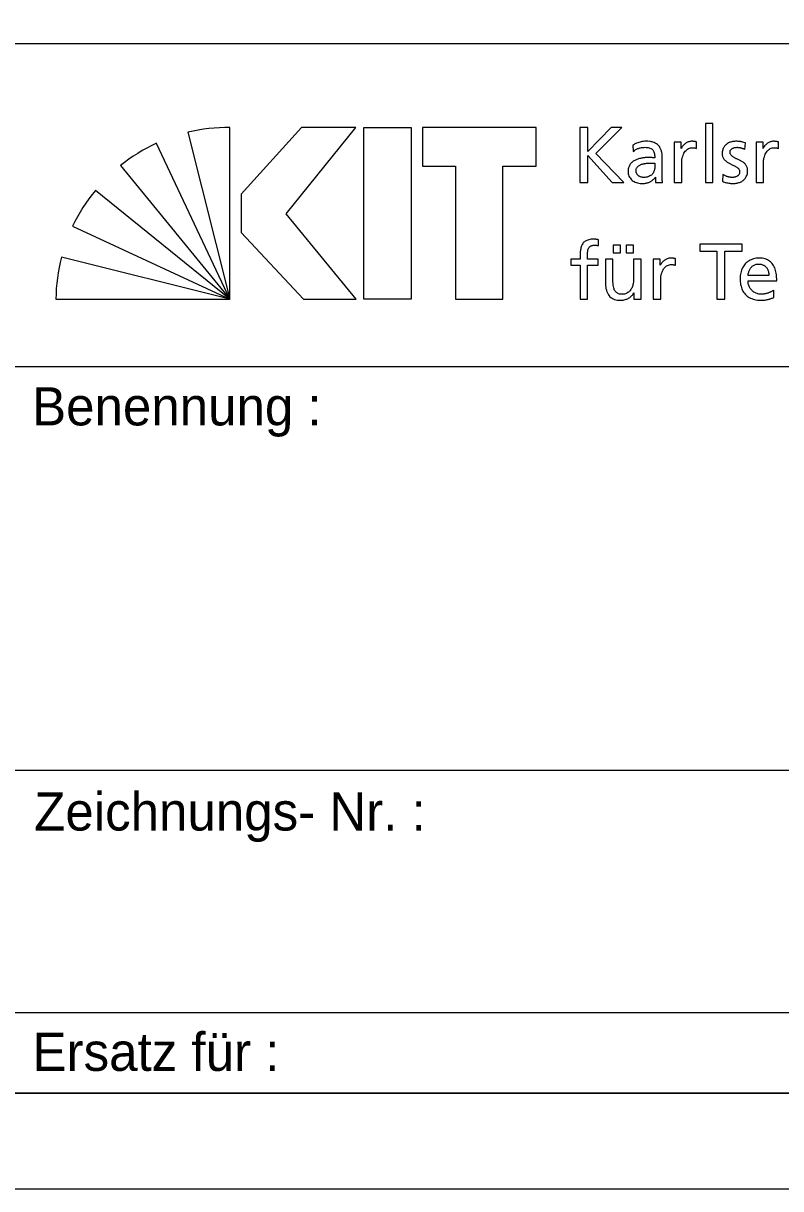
# Model space of a CAD drawing. Extents: x 0 to 23.8, y 0 to 16.8.
# Drawn here: x 22.013 to 22.807, y 0 to 1.221 of the extents above; entities that cross this region are included whole.
import ezdxf

# ---------------------------------------------------------------- set-up
doc = ezdxf.new("R2010")
doc.units = 0
doc.layers.add('90_Plankopf', color=7, linetype='Continuous')

msp = doc.modelspace()

# ---------------------------------------------------------------- linework, layer by layer
at = {"layer": '90_Plankopf'}
for p, q in [((20.1224, 1.1998), (23.68, 1.1998)), ((20.1224, 1.1998), (23.68, 1.1998)), ((22.2296, 0.9317), (22.2296, 1.1117)), ((22.5962, 1.1117), (22.5962, 1.0541)), ((22.1855, 1.1067), (22.2296, 0.9317)), ((22.2296, 0.9317), (22.1527, 1.095)), ((22.6516, 1.0932), (22.652, 1.0866)), ((22.7185, 1.0897), (22.7185, 1.0966)), ((22.7691, 1.0888), (22.7698, 1.0956)), ((22.8042, 1.0897), (22.8042, 1.0966)), ((22.6824, 1.0624), (22.6824, 1.0798)), ((22.1149, 1.0717), (22.2296, 0.9317)), ((22.6746, 1.0742), (22.6746, 1.0705)), ((22.7459, 1.0624), (22.7455, 1.0554)), ((22.5962, 1.0541), (22.6044, 1.0541)), ((22.6301, 1.0541), (22.6422, 1.0541)), ((22.2296, 0.9317), (22.0887, 1.0457)), ((22.0648, 1.0083), (22.2296, 0.9317)), ((22.6155, 0.9879), (22.6158, 0.9941)), ((22.2296, 0.9317), (22.0532, 0.9758)), ((22.6965, 0.9673), (22.6965, 0.9742)), ((22.7941, 0.9568), (22.7723, 0.9568)), ((22.7723, 0.951), (22.8024, 0.951)), ((22.7992, 0.9335), (22.7992, 0.9412)), ((22.0473, 0.9317), (22.2296, 0.9317)), ((22, 0.8614), (23.68, 0.8614)), ((22, 0.4384), (23.68, 0.4384)), ((22, 0.1846), (23.68, 0.1846)), ((23.68, 0.1), (20.1224, 0.1)), ((20.356, 0.1), (23.68, 0.1)), ((20.356, 0.1), (23.68, 0.1))]:
    msp.add_line(p, q, dxfattribs=at)
for points in [[(0, 0), (23.78, 0), (23.78, 16.82), (0, 16.82)], [(0.5, 0.1), (23.68, 0.1), (23.68, 16.72), (0.5, 16.72)], [(22.3613, 1.1117), (22.3047, 1.1117), (22.2415, 1.042), (22.2415, 1.0018), (22.3068, 0.9317), (22.3617, 0.9317), (22.2884, 1.0213)], [(22.4194, 1.1117), (22.4194, 0.9317), (22.37, 0.9317), (22.37, 1.1117)], [(22.4312, 1.1117), (22.4312, 1.0712), (22.466, 1.0712), (22.466, 0.9317), (22.5154, 0.9317), (22.5154, 1.0712), (22.5502, 1.0712), (22.5502, 1.1117)]]:
    msp.add_lwpolyline(points, close=True, dxfattribs=at)
for points in [[(22.6422, 1.0541), (22.6129, 1.0845), (22.64, 1.1117), (22.629, 1.1117), (22.6044, 1.0864), (22.6044, 1.1117), (22.5962, 1.1117)], [(22.7276, 1.0541), (22.7354, 1.0541), (22.7354, 1.116), (22.7276, 1.116), (22.7276, 1.0541)], [(22.7024, 1.0897), (22.7023, 1.0897), (22.7023, 1.0962), (22.695, 1.0962), (22.695, 1.0541), (22.7028, 1.0541), (22.7028, 1.0733)], [(22.7881, 1.0897), (22.788, 1.0897), (22.788, 1.0962), (22.7807, 1.0962), (22.7807, 1.0541), (22.7885, 1.0541), (22.7885, 1.0733)], [(22.6044, 1.0541), (22.6044, 1.0823), (22.6301, 1.0541)], [(22.6753, 1.0596), (22.6754, 1.0596), (22.6754, 1.0541), (22.6827, 1.0541)], [(22.7398, 0.9317), (22.7481, 0.9317), (22.7481, 0.9821), (22.766, 0.9821), (22.766, 0.9893), (22.7219, 0.9893), (22.7219, 0.9821), (22.7398, 0.9821), (22.7398, 0.9317)], [(22.5965, 0.9777), (22.5965, 0.9738), (22.5866, 0.9738), (22.5866, 0.9676), (22.5965, 0.9676), (22.5965, 0.9317), (22.6042, 0.9317), (22.6042, 0.9676), (22.6154, 0.9676), (22.6154, 0.9738), (22.6042, 0.9738), (22.6042, 0.9784)], [(22.6311, 0.9885), (22.6311, 0.9803), (22.6388, 0.9803), (22.6388, 0.9885), (22.6311, 0.9885)], [(22.6446, 0.9885), (22.6446, 0.9803), (22.6524, 0.9803), (22.6524, 0.9885), (22.6446, 0.9885)], [(22.6308, 0.952), (22.6308, 0.9738), (22.6231, 0.9738), (22.6231, 0.9488)], [(22.6603, 0.9317), (22.6603, 0.9738), (22.6525, 0.9738), (22.6525, 0.9543)], [(22.6804, 0.9673), (22.6803, 0.9673), (22.6803, 0.9738), (22.673, 0.9738), (22.673, 0.9317), (22.6808, 0.9317), (22.6808, 0.9509)], [(22.6526, 0.9384), (22.6528, 0.9384), (22.6528, 0.9317), (22.6603, 0.9317)]]:
    msp.add_lwpolyline(points, dxfattribs=at)
for centre, start, end in [((22.229, 0.9211), 89.8053, 103.1895), ((22.2332, 0.9224), 115.0126, 128.3968), ((22.2363, 0.9253), 140.7898, 154.174), ((22.2378, 0.9288), 165.7222, 179.1064)]:
    msp.add_arc(centre, 0.1906, start, end, dxfattribs=at)
for points in [[(22.6824, 1.0798), (22.6824, 1.0836), (22.6818, 1.0868), (22.6807, 1.0894), (22.6795, 1.092), (22.6777, 1.0939), (22.6752, 1.0952), (22.6727, 1.0965), (22.6694, 1.0972), (22.6654, 1.0972), (22.6628, 1.0972), (22.6603, 1.0968), (22.658, 1.0961), (22.6556, 1.0954), (22.6535, 1.0944), (22.6516, 1.0932)], [(22.652, 1.0866), (22.6531, 1.0875), (22.6543, 1.0883), (22.6556, 1.0889), (22.6569, 1.0896), (22.6583, 1.0901), (22.6598, 1.0904), (22.6613, 1.0908), (22.6627, 1.0909), (22.6642, 1.0909), (22.6668, 1.0909), (22.6688, 1.0905), (22.6704, 1.0897), (22.6719, 1.0889), (22.673, 1.0877), (22.6736, 1.086), (22.6743, 1.0844), (22.6746, 1.0824), (22.6746, 1.0799)], [(22.7185, 1.0966), (22.718, 1.0967), (22.7175, 1.0968), (22.717, 1.0969), (22.7165, 1.097), (22.716, 1.0971), (22.7154, 1.0971), (22.7148, 1.0972), (22.7142, 1.0972), (22.7134, 1.0972), (22.7119, 1.0972), (22.7105, 1.0969), (22.709, 1.0962), (22.7076, 1.0956), (22.7064, 1.0947), (22.7052, 1.0936), (22.7041, 1.0925), (22.7031, 1.0912), (22.7024, 1.0897)], [(22.7028, 1.0733), (22.7028, 1.0768), (22.7033, 1.0799), (22.7042, 1.0824), (22.7051, 1.085), (22.7065, 1.087), (22.7082, 1.0883), (22.7099, 1.0897), (22.7119, 1.0904), (22.7142, 1.0904), (22.7149, 1.0904), (22.7156, 1.0904), (22.7164, 1.0903), (22.7171, 1.0902), (22.7178, 1.09), (22.7185, 1.0897)], [(22.7698, 1.0956), (22.7683, 1.096), (22.7667, 1.0964), (22.7652, 1.0967), (22.7636, 1.097), (22.7619, 1.0972), (22.7601, 1.0972), (22.7581, 1.0972), (22.7561, 1.0969), (22.7543, 1.0964), (22.7525, 1.0959), (22.7509, 1.0951), (22.7496, 1.094), (22.7482, 1.0929), (22.7472, 1.0916), (22.7464, 1.09), (22.7457, 1.0883), (22.7453, 1.0864), (22.7453, 1.0842), (22.7453, 1.0826), (22.7456, 1.0811), (22.7463, 1.0799), (22.7469, 1.0787), (22.7478, 1.0776), (22.7489, 1.0767), (22.75, 1.0758), (22.7512, 1.075), (22.7525, 1.0743), (22.7538, 1.0736), (22.7551, 1.0729), (22.7563, 1.0723), (22.7576, 1.0717), (22.7588, 1.0711), (22.7599, 1.0704), (22.761, 1.0698), (22.7619, 1.0691), (22.7625, 1.0683), (22.7632, 1.0675), (22.7635, 1.0665), (22.7635, 1.0654), (22.7635, 1.0643), (22.7633, 1.0633), (22.7628, 1.0626), (22.7623, 1.0618), (22.7617, 1.0612), (22.7609, 1.0607), (22.7601, 1.0602), (22.7593, 1.0599), (22.7583, 1.0597), (22.7574, 1.0595), (22.7565, 1.0594), (22.7556, 1.0594), (22.7548, 1.0594), (22.7539, 1.0595), (22.7528, 1.0597), (22.7517, 1.0599), (22.7505, 1.0603), (22.7493, 1.0607), (22.7481, 1.0612), (22.747, 1.0617), (22.7459, 1.0624)], [(22.7455, 1.0554), (22.7473, 1.0545), (22.7492, 1.0539), (22.7512, 1.0536), (22.7531, 1.0532), (22.7551, 1.0531), (22.7571, 1.0531), (22.759, 1.0531), (22.7608, 1.0534), (22.7625, 1.0539), (22.7643, 1.0544), (22.7659, 1.0552), (22.7673, 1.0563), (22.7686, 1.0574), (22.7697, 1.0588), (22.7705, 1.0604), (22.7714, 1.0621), (22.7718, 1.064), (22.7718, 1.0662), (22.7718, 1.0682), (22.7714, 1.0698), (22.7708, 1.0711), (22.7701, 1.0724), (22.7692, 1.0736), (22.7682, 1.0745), (22.7671, 1.0754), (22.7659, 1.0762), (22.7646, 1.0769), (22.7633, 1.0776), (22.762, 1.0782), (22.7607, 1.0787), (22.7594, 1.0793), (22.7582, 1.0799), (22.7572, 1.0805), (22.7561, 1.0812), (22.7552, 1.0819), (22.7545, 1.0827), (22.7539, 1.0836), (22.7536, 1.0846), (22.7535, 1.0858), (22.7536, 1.087), (22.7539, 1.0879), (22.7546, 1.0887), (22.7553, 1.0894), (22.7562, 1.09), (22.7573, 1.0904), (22.7584, 1.0908), (22.7596, 1.0909), (22.761, 1.0909), (22.7614, 1.0909), (22.762, 1.0909), (22.7628, 1.0908), (22.7635, 1.0906), (22.7643, 1.0905), (22.7651, 1.0903), (22.7659, 1.0901), (22.7667, 1.0898), (22.7674, 1.0896), (22.7681, 1.0893), (22.7687, 1.0891), (22.7691, 1.0888)], [(22.8042, 1.0966), (22.8037, 1.0967), (22.8032, 1.0968), (22.8027, 1.0969), (22.8022, 1.097), (22.8017, 1.0971), (22.8011, 1.0971), (22.8005, 1.0972), (22.7999, 1.0972), (22.7991, 1.0972), (22.7976, 1.0972), (22.7962, 1.0969), (22.7947, 1.0962), (22.7933, 1.0956), (22.7921, 1.0947), (22.7909, 1.0936), (22.7898, 1.0925), (22.7888, 1.0912), (22.7881, 1.0897)], [(22.7885, 1.0733), (22.7885, 1.0768), (22.789, 1.0799), (22.7899, 1.0824), (22.7908, 1.085), (22.7922, 1.087), (22.7939, 1.0883), (22.7956, 1.0897), (22.7976, 1.0904), (22.7999, 1.0904), (22.8006, 1.0904), (22.8013, 1.0904), (22.8021, 1.0903), (22.8028, 1.0902), (22.8035, 1.09), (22.8042, 1.0897)], [(22.6746, 1.0799), (22.6736, 1.08), (22.6727, 1.08), (22.6718, 1.0801), (22.6709, 1.0801), (22.67, 1.0801), (22.6692, 1.0801), (22.6683, 1.0801), (22.6674, 1.0801), (22.6664, 1.0801), (22.6647, 1.0801), (22.663, 1.08), (22.6613, 1.0797), (22.6595, 1.0794), (22.6577, 1.0789), (22.656, 1.0783), (22.6543, 1.0776), (22.6528, 1.0768), (22.6514, 1.0757), (22.65, 1.0746), (22.6489, 1.0733), (22.6481, 1.0718), (22.6472, 1.0702), (22.6468, 1.0684), (22.6468, 1.0662), (22.6468, 1.0632), (22.6475, 1.0607), (22.6488, 1.0588), (22.6501, 1.0568), (22.6519, 1.0554), (22.6542, 1.0545), (22.6565, 1.0536), (22.6592, 1.0531), (22.6622, 1.0531), (22.664, 1.0531), (22.6656, 1.0534), (22.667, 1.0538), (22.6684, 1.0542), (22.6697, 1.0547), (22.6707, 1.0554), (22.6718, 1.056), (22.6727, 1.0567), (22.6735, 1.0575), (22.6742, 1.0582), (22.6748, 1.0589), (22.6753, 1.0596)], [(22.6746, 1.0705), (22.6746, 1.0684), (22.6742, 1.0665), (22.6733, 1.0648), (22.6724, 1.0631), (22.6711, 1.0618), (22.6693, 1.0609), (22.6676, 1.0599), (22.6654, 1.0594), (22.6629, 1.0594), (22.662, 1.0594), (22.6611, 1.0596), (22.6602, 1.0598), (22.6593, 1.0601), (22.6584, 1.0606), (22.6576, 1.0611), (22.6569, 1.0617), (22.6562, 1.0625), (22.6558, 1.0633), (22.6553, 1.0641), (22.6551, 1.0651), (22.655, 1.0662), (22.6551, 1.0677), (22.6554, 1.069), (22.6562, 1.0699), (22.6569, 1.0709), (22.6578, 1.0717), (22.659, 1.0723), (22.6601, 1.0729), (22.6614, 1.0733), (22.6627, 1.0736), (22.664, 1.0739), (22.6653, 1.0741), (22.6665, 1.0742), (22.6677, 1.0743), (22.6688, 1.0743), (22.6697, 1.0743), (22.6705, 1.0743), (22.6713, 1.0743), (22.6721, 1.0743), (22.673, 1.0742), (22.6738, 1.0742), (22.6746, 1.0742)], [(22.6827, 1.0541), (22.6826, 1.0545), (22.6826, 1.0551), (22.6825, 1.0557), (22.6825, 1.0564), (22.6824, 1.0573), (22.6824, 1.0584), (22.6824, 1.0595), (22.6824, 1.0608), (22.6824, 1.0624)], [(22.6158, 0.9941), (22.615, 0.9942), (22.6142, 0.9944), (22.6134, 0.9945), (22.6125, 0.9946), (22.6116, 0.9946), (22.6106, 0.9946), (22.6078, 0.9946), (22.6054, 0.9942), (22.6036, 0.9934), (22.6017, 0.9926), (22.6003, 0.9915), (22.5992, 0.99), (22.5982, 0.9885), (22.5975, 0.9867), (22.5971, 0.9847), (22.5967, 0.9826), (22.5965, 0.9803), (22.5965, 0.9777)], [(22.6042, 0.9784), (22.6042, 0.9798), (22.6043, 0.9811), (22.6045, 0.9823), (22.6046, 0.9835), (22.605, 0.9846), (22.6055, 0.9855), (22.606, 0.9864), (22.6068, 0.9871), (22.6078, 0.9876), (22.6088, 0.9881), (22.6101, 0.9883), (22.6118, 0.9883), (22.6124, 0.9883), (22.6131, 0.9883), (22.6138, 0.9882), (22.6144, 0.9881), (22.615, 0.988), (22.6155, 0.9879)], [(22.6965, 0.9742), (22.696, 0.9743), (22.6955, 0.9744), (22.695, 0.9745), (22.6945, 0.9746), (22.694, 0.9747), (22.6934, 0.9747), (22.6928, 0.9748), (22.6922, 0.9748), (22.6914, 0.9748), (22.6899, 0.9748), (22.6885, 0.9745), (22.687, 0.9738), (22.6856, 0.9732), (22.6844, 0.9723), (22.6832, 0.9712), (22.6821, 0.9701), (22.6811, 0.9688), (22.6804, 0.9673)], [(22.6808, 0.9509), (22.6808, 0.9544), (22.6813, 0.9575), (22.6822, 0.96), (22.6832, 0.9626), (22.6845, 0.9646), (22.6862, 0.9659), (22.6879, 0.9673), (22.6899, 0.968), (22.6922, 0.968), (22.6929, 0.9681), (22.6936, 0.968), (22.6944, 0.9679), (22.6951, 0.9678), (22.6958, 0.9676), (22.6965, 0.9673)], [(22.8024, 0.951), (22.8024, 0.9544), (22.8021, 0.9576), (22.8014, 0.9605), (22.8008, 0.9634), (22.7998, 0.9659), (22.7984, 0.968), (22.7969, 0.9701), (22.795, 0.9718), (22.7926, 0.973), (22.7902, 0.9742), (22.7873, 0.9748), (22.7838, 0.9748), (22.7808, 0.9748), (22.7781, 0.9743), (22.7757, 0.9732), (22.7733, 0.9722), (22.7712, 0.9707), (22.7695, 0.9688), (22.7677, 0.9669), (22.7664, 0.9647), (22.7655, 0.9621), (22.7646, 0.9595), (22.7641, 0.9567), (22.7641, 0.9535), (22.7641, 0.9501), (22.7645, 0.947), (22.7654, 0.9442), (22.7662, 0.9414), (22.7676, 0.939), (22.7694, 0.937), (22.7712, 0.935), (22.7734, 0.9334), (22.7762, 0.9324), (22.7789, 0.9313), (22.7821, 0.9308), (22.7859, 0.9307), (22.7882, 0.9308), (22.7901, 0.9309), (22.7917, 0.9312), (22.7933, 0.9315), (22.7947, 0.9319), (22.7959, 0.9323), (22.7971, 0.9327), (22.7982, 0.9331), (22.7992, 0.9335)], [(22.7723, 0.9568), (22.7725, 0.9582), (22.7728, 0.9596), (22.7733, 0.9609), (22.7738, 0.9623), (22.7744, 0.9636), (22.7754, 0.9647), (22.7762, 0.9659), (22.7774, 0.9668), (22.7787, 0.9675), (22.7801, 0.9682), (22.7817, 0.9685), (22.7836, 0.9685), (22.7853, 0.9685), (22.7868, 0.9682), (22.7881, 0.9676), (22.7894, 0.967), (22.7905, 0.9662), (22.7914, 0.9651), (22.7923, 0.964), (22.793, 0.9628), (22.7934, 0.9614), (22.7939, 0.96), (22.7941, 0.9584), (22.7941, 0.9568)], [(22.6525, 0.9543), (22.6525, 0.9518), (22.6523, 0.9494), (22.6518, 0.9473), (22.6513, 0.9452), (22.6505, 0.9434), (22.6495, 0.9418), (22.6484, 0.9403), (22.6471, 0.9391), (22.6455, 0.9383), (22.6439, 0.9374), (22.6419, 0.937), (22.6397, 0.937), (22.6375, 0.9371), (22.6357, 0.9378), (22.6344, 0.9389), (22.6331, 0.94), (22.6322, 0.9417), (22.6316, 0.9439), (22.6311, 0.946), (22.6308, 0.9488), (22.6308, 0.952)], [(22.6231, 0.9488), (22.6231, 0.945), (22.6236, 0.9418), (22.6247, 0.9391), (22.6259, 0.9364), (22.6276, 0.9343), (22.6299, 0.9329), (22.6322, 0.9315), (22.6352, 0.9308), (22.6388, 0.9307), (22.6408, 0.9308), (22.6427, 0.9311), (22.6445, 0.9317), (22.6463, 0.9323), (22.6479, 0.9332), (22.6493, 0.9343), (22.6507, 0.9354), (22.6518, 0.9368), (22.6526, 0.9384)], [(22.7992, 0.9412), (22.7987, 0.9408), (22.798, 0.9404), (22.797, 0.9399), (22.7961, 0.9394), (22.7951, 0.939), (22.7939, 0.9385), (22.7927, 0.9381), (22.7914, 0.9377), (22.7901, 0.9374), (22.7888, 0.9372), (22.7875, 0.937), (22.7862, 0.937), (22.7843, 0.937), (22.7826, 0.9374), (22.7809, 0.938), (22.7793, 0.9387), (22.7778, 0.9397), (22.7765, 0.9409), (22.7752, 0.9421), (22.7742, 0.9436), (22.7735, 0.9453), (22.7727, 0.9471), (22.7723, 0.949), (22.7723, 0.951)]]:
    msp.add_open_spline(points, degree=3, dxfattribs=at)

# ---------------------------------------------------------------- texts
for s, p in [('Benennung :', (22.0223, 0.7996)), ('Zeichnungs- Nr. :', (22.0245, 0.3752)), ('Ersatz für :', (22.0228, 0.1234))]:
    msp.add_text(s, height=0.04, dxfattribs=at).set_placement(p)

doc.saveas('drawing.dxf')
